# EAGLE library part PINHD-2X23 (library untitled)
PIN HEADER
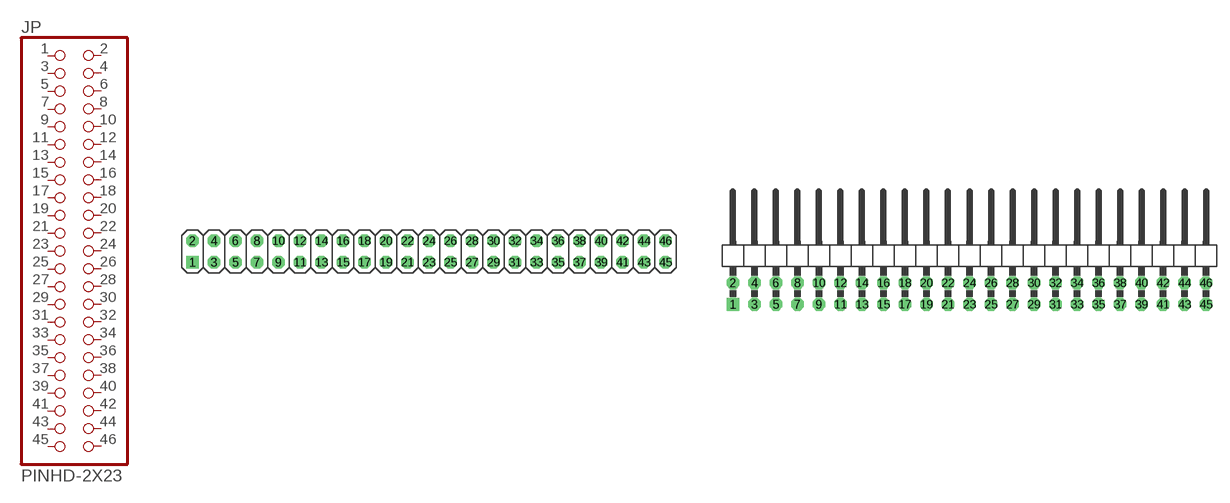
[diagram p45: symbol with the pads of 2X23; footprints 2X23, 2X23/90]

Designator prefix JP

## PINHD-2X23_2.54  [2X23]
1  1  pas
2  2  pas
3  3  pas
4  4  pas
5  5  pas
6  6  pas
7  7  pas
8  8  pas
9  9  pas
10  10  pas
11  11  pas
12  12  pas
13  13  pas
14  14  pas
15  15  pas
16  16  pas
17  17  pas
18  18  pas
19  19  pas
20  20  pas
21  21  pas
22  22  pas
23  23  pas
24  24  pas
25  25  pas
26  26  pas
27  27  pas
28  28  pas
29  29  pas
30  30  pas
31  31  pas
32  32  pas
33  33  pas
34  34  pas
35  35  pas
36  36  pas
37  37  pas
38  38  pas
39  39  pas
40  40  pas
41  41  pas
42  42  pas
43  43  pas
44  44  pas
45  45  pas
46  46  pas

## PINHD-2X23_2.54-90°  [2X23/90]
Pads as for 2X23

## PINHD-2X23_2.00  [2X23M]
Pads as for 2X23

## PINHD-2X23_2.54-SMD  [2X23SMD]
Pads as for 2X23

## PINHD-2X23_2.54-SMD-90°  [2X23SMD/90]
Pads as for 2X23

## Footprint 2X23 (pad centres in mm)
PIN HEADER - 2.54
drill 1.016 square: 1 -25.4,-1.27
drill 1.016 octagon: 2 -25.4,1.27; 3 -22.86,-1.27; 4 -22.86,1.27; 5 -20.32,-1.27; 6 -20.32,1.27; 7 -17.78,-1.27; 8 -17.78,1.27; 9 -15.24,-1.27; 10 -15.24,1.27; 11 -12.7,-1.27; 12 -12.7,1.27; 13 -10.16,-1.27; 14 -10.16,1.27; 15 -7.62,-1.27; 16 -7.62,1.27; 17 -5.08,-1.27; 18 -5.08,1.27; 19 -2.54,-1.27; 20 -2.54,1.27; 21 0,-1.27; 22 0,1.27; 23 2.54,-1.27; 24 2.54,1.27; 25 5.08,-1.27; 26 5.08,1.27; 27 7.62,-1.27; 28 7.62,1.27; 29 10.16,-1.27; 30 10.16,1.27; 31 12.7,-1.27; 32 12.7,1.27; 33 15.24,-1.27; 34 15.24,1.27; 35 17.78,-1.27; 36 17.78,1.27; 37 20.32,-1.27; 38 20.32,1.27; 39 22.86,-1.27; 40 22.86,1.27; 41 25.4,-1.27; 42 25.4,1.27; 43 27.94,-1.27; 44 27.94,1.27; 45 30.48,-1.27; 46 30.48,1.27

## Footprint 2X23/90 (pad centres in mm)
PIN HEADER - 2.54 90°
drill 1.016 square: 1 -24.13,-6.35
drill 1.016 octagon: 2 -24.13,-3.81; 3 -21.59,-6.35; 4 -21.59,-3.81; 5 -19.05,-6.35; 6 -19.05,-3.81; 7 -16.51,-6.35; 8 -16.51,-3.81; 9 -13.97,-6.35; 10 -13.97,-3.81; 11 -11.43,-6.35; 12 -11.43,-3.81; 13 -8.89,-6.35; 14 -8.89,-3.81; 15 -6.35,-6.35; 16 -6.35,-3.81; 17 -3.81,-6.35; 18 -3.81,-3.81; 19 -1.27,-6.35; 20 -1.27,-3.81; 21 1.27,-6.35; 22 1.27,-3.81; 23 3.81,-6.35; 24 3.81,-3.81; 25 6.35,-6.35; 26 6.35,-3.81; 27 8.89,-6.35; 28 8.89,-3.81; 29 11.43,-6.35; 30 11.43,-3.81; 31 13.97,-6.35; 32 13.97,-3.81; 33 16.51,-6.35; 34 16.51,-3.81; 35 19.05,-6.35; 36 19.05,-3.81; 37 21.59,-6.35; 38 21.59,-3.81; 39 24.13,-6.35; 40 24.13,-3.81; 41 26.67,-6.35; 42 26.67,-3.81; 43 29.21,-6.35; 44 29.21,-3.81; 45 31.75,-6.35; 46 31.75,-3.81

## Footprint 2X23M (pad centres in mm)
PIN HEADER - 2
drill 0.914 square: 1 -21,-1
drill 0.914 round: 2 -21,1; 3 -19,-1; 4 -19,1; 5 -17,-1; 6 -17,1; 7 -15,-1; 8 -15,1; 9 -13,-1; 10 -13,1; 11 -11,-1; 12 -11,1; 13 -9,-1; 14 -9,1; 15 -7,-1; 16 -7,1; 17 -5,-1; 18 -5,1; 19 -3,-1; 20 -3,1; 21 -1,-1; 22 -1,1; 23 1,-1; 24 1,1; 25 3,-1; 26 3,1; 27 5,-1; 28 5,1; 29 7,-1; 30 7,1; 31 9,-1; 32 9,1; 33 11,-1; 34 11,1; 35 13,-1; 36 13,1; 37 15,-1; 38 15,1; 39 17,-1; 40 17,1; 41 19,-1; 42 19,1; 43 21,-1; 44 21,1; 45 23,-1; 46 23,1

## Footprint 2X23SMD (pad centres in mm)
PIN HEADER - 2.54 SMD
smd 1.016 x 3.302: 1 -1.27,-3.81; 2 -1.27,1.27; 3 1.27,-3.81; 4 1.27,1.27; 5 3.81,-3.81; 6 3.81,1.27; 7 6.35,-3.81; 8 6.35,1.27; 9 8.89,-3.81; 10 8.89,1.27; 11 11.43,-3.81; 12 11.43,1.27; 13 13.97,-3.81; 14 13.97,1.27; 15 16.51,-3.81; 16 16.51,1.27; 17 19.05,-3.81; 18 19.05,1.27; 19 21.59,-3.81; 20 21.59,1.27; 21 24.13,-3.81; 22 24.13,1.27; 23 26.67,-3.81; 24 26.67,1.27; 25 29.21,-3.81; 26 29.21,1.27; 27 31.75,-3.81; 28 31.75,1.27; 29 34.29,-3.81; 30 34.29,1.27; 31 36.83,-3.81; 32 36.83,1.27; 33 39.37,-3.81; 34 39.37,1.27; 35 41.91,-3.81; 36 41.91,1.27; 37 44.45,-3.81; 38 44.45,1.27; 39 46.99,-3.81; 40 46.99,1.27; 41 49.53,-3.81; 42 49.53,1.27; 43 52.07,-3.81; 44 52.07,1.27; 45 54.61,-3.81; 46 54.61,1.27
